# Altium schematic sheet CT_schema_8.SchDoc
size 254 x 194 mm
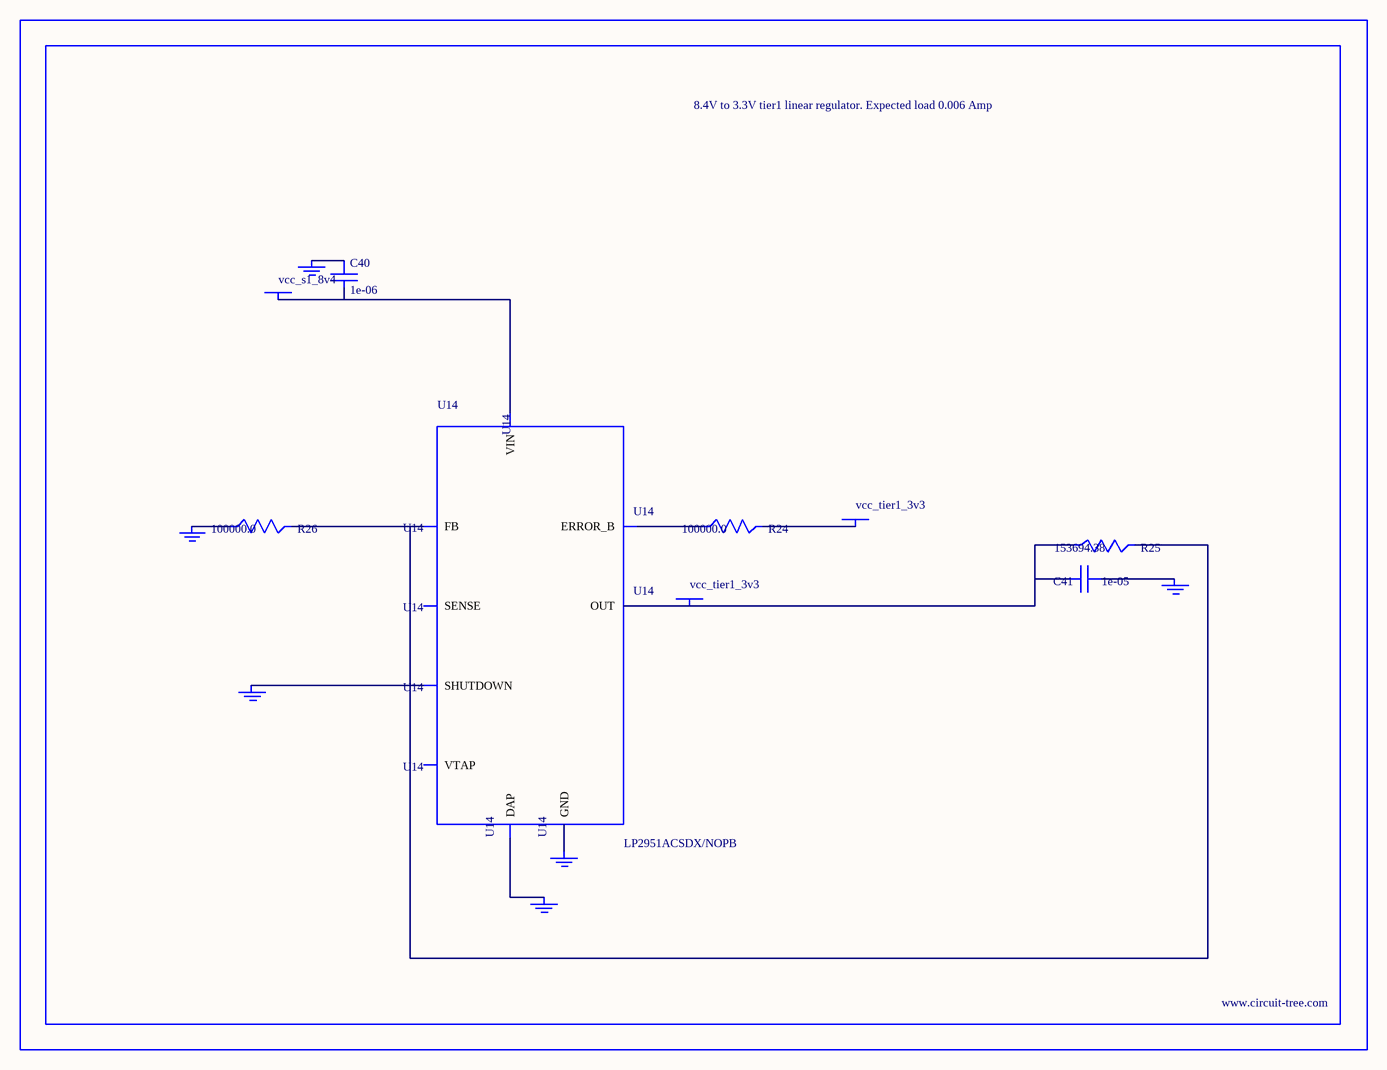
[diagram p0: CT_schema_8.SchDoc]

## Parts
BORDER7  (no value)
C40  1e-06  [C0603]
C41  1e-05  [C1210]
GND_INSTANCE_7_0  (no value)
GND_INSTANCE_7_1  (no value)
GND_INSTANCE_7_2  (no value)
GND_INSTANCE_7_3  (no value)
GND_INSTANCE_7_4  (no value)
GND_INSTANCE_7_5  (no value)
POWER_INSTANCE_7_0  vcc_tier1_3v3
POWER_INSTANCE_7_1  vcc_s1_8v4
POWER_INSTANCE_7_2  vcc_tier1_3v3
R24  100000.0  [R0603]
R25  153694.38  [R0603]
R26  100000.0  [R0603]
U14  LP2951ACSDX/NOPB  [WSON-8]

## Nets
NetC40_1: C40.1 GND_INSTANCE_7_3.0(GND)
NetC40_2: C40.2 POWER_INSTANCE_7_1.0(PWR) U14.8(VIN)
NetC41_1: C41.1 GND_INSTANCE_7_0.0(GND)
NetC41_2: C41.2 POWER_INSTANCE_7_2.0(PWR) R25.1 U14.1(OUT)
NetGND_INSTANCE_7_1_0: GND_INSTANCE_7_1.0(GND) U14.3(SHUTDOWN)
NetGND_INSTANCE_7_2_0: GND_INSTANCE_7_2.0(GND) R26.1
NetGND_INSTANCE_7_4_0: GND_INSTANCE_7_4.0(GND) U14.PAD(DAP)
NetGND_INSTANCE_7_5_0: GND_INSTANCE_7_5.0(GND) U14.4(GND)
NetPOWER_INSTANCE_7_0_0: POWER_INSTANCE_7_0.0(PWR) R24.2
NetR24_1: R24.1 U14.5(ERROR_B)
NetR25_2: R25.2 R26.2 U14.7(FB)

Not connected (* = marked no-connect by the designer): U14 2(SENSE) 6(VTAP)

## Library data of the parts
BORDER7 = BORDER_PAGE7
C40 = C0603C105K3RACTU
C41 = GRM32DR61E106MA12L
GND_INSTANCE_7_0-GND_INSTANCE_7_5 = GND
POWER_INSTANCE_7_0-POWER_INSTANCE_7_2 = PWR
R24 R26 = RC0603JR-07100KL
R25 = R25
